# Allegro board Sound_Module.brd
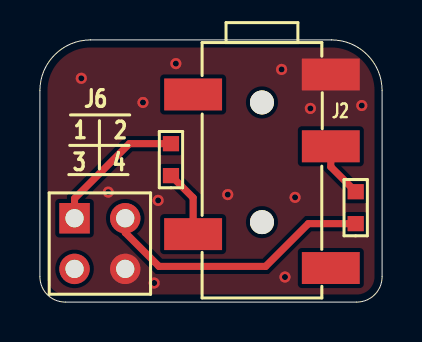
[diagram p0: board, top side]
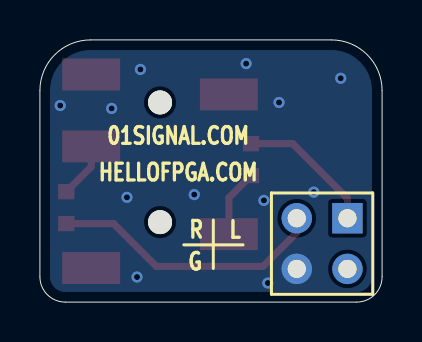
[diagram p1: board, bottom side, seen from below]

Outline 17.15 x 13.14 mm; copper layers: TOP, BOTTOM. Coordinates in mm from the lower left corner of the outline.
Outline path: 0,10.6 arc(0.74,12.4) 2.54,13.14 14.61,13.14 arc(16.41,12.4) 17.15,10.6 17.15,1.27 arc(16.78,0.37) 15.88,0 1.27,0 arc(0.37,0.37) 0,1.27 0,10.6

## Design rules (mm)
constraint set DEFAULT: min track width 0.203

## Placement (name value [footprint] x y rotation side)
J1  2X2  [ISP2X2]  1.74 1.66 270 top
J2  PJ_327A_C  [PJ_327A]  11.13 13.01 0 top
NOREF  -  []  -258.21 -249.2 0 top
NOREF#2  -  []  -258.21 -249.2 0 top
NOREF#3  -  []  -258.21 -249.2 0 top
R5  50R  [R0603_1]  6.57 7.14 90 top
R6  50R  [R0603_1]  15.83 4.73 90 top

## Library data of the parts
J1 = CON_JACK_31
J2 = 1117S_15.3V
R5 R6 = R

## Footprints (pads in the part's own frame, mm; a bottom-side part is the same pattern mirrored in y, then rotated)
ISP2X2
  rect 1.524x1.524 hole 0.914: 1(-2.54,0)
  round 1.524 hole 0.914: 2(0,0) 3(0,2.54) 4(-2.54,2.54)
PJ_327A
  round 1.2 hole 1.2 unplated: (0,-3) (0,-9)
  rect 2.9x1.6 smd: 1(3.45,-1.6) 2(-3.45,-9.6) 3(3.45,-5.2) 4(3.45,-11.3) 5(-3.45,-2.6)
R0603_1
  rect 0.762x0.813 smd: 1(-0.8,0) 2(0.8,0)

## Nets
GND: J1.3 J2.1
J6_1: J1.1 R5.2
J6_2: J1.4 R6.1
J6_3: J1.2
N17506297: J2.2 R5.1
N17506320: J2.3 R6.2

Pads without a net: J2 4 5

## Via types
v1: diameter 0.559, hole 0.305, TOP to BOTTOM, 12 vias

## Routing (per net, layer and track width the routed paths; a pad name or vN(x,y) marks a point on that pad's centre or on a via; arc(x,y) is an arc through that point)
GND:
  vias: v1(2.07,11.22) v1(3.42,5.51) v1(5.17,10.01) v1(5.72,0.96) v1(5.92,5.1) v1(6.81,11.95) v1(9.41,5.39) v1(12.11,11.66) v1(12.28,1.26) v1(12.79,5.25) v1(13.55,9.71) v1(16.13,9.85)
J6_1: length 7
  TOP w0.356: R5.2 4.48,7.94 1.74,5.19 J1.1
J6_2: length 13.9
  TOP w0.356: J1.4 4.28,3.48 5.97,1.79 11.31,1.79 13.46,3.93 R6.1
N17506297: length 3.4
  TOP w0.356: J2.2 7.68,5.23 R5.1
N17506320: length 2.8
  TOP w0.356: J2.3 14.58,6.78 R6.2

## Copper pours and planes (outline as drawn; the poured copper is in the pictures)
GND on TOP: 0.38,10.6 1.01,12.13 2.54,12.76 14.61,12.76 16.14,12.13 16.77,10.6 16.77,1.27 16.51,0.64 15.88,0.38 1.27,0.38 0.64,0.64 0.38,1.27
GND on BOTTOM: 0.51,10.6 1.1,12.04 2.54,12.63 14.61,12.63 16.05,12.04 16.64,10.6 16.64,1.27 16.42,0.73 15.88,0.51 1.27,0.51 0.73,0.73 0.51,1.27

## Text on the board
Ref Des/Silkscreen Bottom: L | R | G | 01SIGNAL.COM | HELLOFPGA.COM
Ref Des/Silkscreen Top: 3 | 1 | J6 | 4 | 2
NCLEGEND-1-2: FIGURE | FINISHED_SIZE | 12.0 | 36.0 | 47.244 | DRILL CHART: TOP to BOTTOM | ALL UNITS ARE IN MILS | PLATED | NON-PLATED | QTY | 12 | 3 | 1 | 2
